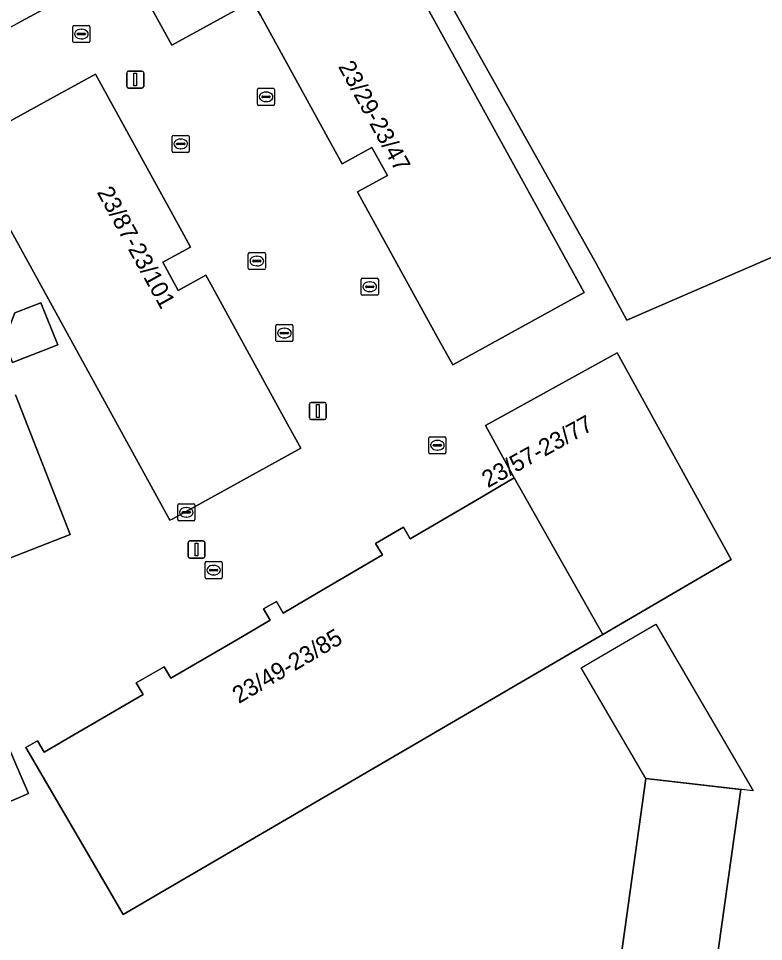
# Model space of a CAD drawing. Extents: x 161087 to 161926, y 382572 to 383873.
# Drawn here: x 161788.9 to 161832.5, y 382703.7 to 382757.7 of the extents above; entities that cross this region are included whole.
import ezdxf

# ---------------------------------------------------------------- set-up
doc = ezdxf.new("R2010")
doc.units = 0
for name, color, linetype in [('IMGEO_Brandkraan', 7, 'Continuous'), ('IMGEO_Erf', 7, 'Continuous'), ('IMGEO_Kolk', 7, 'Continuous'), ('IMGEO_Lichtmast', 7, 'Continuous'), ('IMGEO_Pand', 7, 'Continuous'), ('IMGEO_Pand_nummerreeks', 7, 'Continuous'), ('IMGEO_Pand_vergunning_verleend', 7, 'Continuous')]:
    doc.layers.add(name, color=color, linetype=linetype)

msp = doc.modelspace()

# ---------------------------------------------------------------- linework, layer by layer
at = {"layer": 'IMGEO_Brandkraan'}
for p, q in [((161802.377, 382743.063), (161802.377, 382743.915)), ((161802.452, 382743.989), (161803.304, 382743.989)), ((161803.378, 382743.915), (161803.378, 382743.063)), ((161802.636, 382743.483), (161802.636, 382743.495)), ((161803.074, 382743.446), (161802.676, 382743.446)), ((161802.679, 382743.532), (161803.077, 382743.532)), ((161802.865, 382743.769), (161802.89, 382743.769)), ((161803.12, 382743.495), (161803.12, 382743.483)), ((161803.304, 382742.989), (161802.452, 382742.989)), ((161802.888, 382743.209), (161802.863, 382743.209)), ((161798.253, 382728.36), (161798.253, 382729.212)), ((161798.328, 382729.286), (161799.18, 382729.286)), ((161798.512, 382728.78), (161798.512, 382728.792)), ((161798.555, 382728.829), (161798.953, 382728.829)), ((161798.741, 382729.066), (161798.766, 382729.066)), ((161798.996, 382728.792), (161798.996, 382728.78)), ((161799.254, 382729.212), (161799.254, 382728.36)), ((161799.18, 382728.286), (161798.328, 382728.286)), ((161798.95, 382728.743), (161798.552, 382728.743)), ((161798.764, 382728.506), (161798.739, 382728.506))]:
    msp.add_line(p, q, dxfattribs=at)
for points in [[(161802.377, 382743.063), (161802.377, 382743.915)], [(161802.452, 382743.989), (161803.304, 382743.989)], [(161803.378, 382743.915), (161803.378, 382743.063)], [(161803.304, 382742.989), (161802.452, 382742.989)], [(161798.253, 382728.36), (161798.253, 382729.212)], [(161798.328, 382729.286), (161799.18, 382729.286)], [(161799.254, 382729.212), (161799.254, 382728.36)], [(161799.18, 382728.286), (161798.328, 382728.286)]]:
    msp.add_lwpolyline(points, dxfattribs=at)
for centre, radius, start, end in [((161802.454, 382743.913), 0.0765, 91.552, 178.448), ((161802.454, 382743.913), 0.0765, 91.552, 178.448), ((161803.302, 382743.913), 0.0765, 1.552, 88.448), ((161803.302, 382743.913), 0.0765, 1.552, 88.448), ((161802.676, 382743.492), 0.0403, 85.8775, 175.7526), ((161802.673, 382743.482), 0.0366, 178.938, 274.7102), ((161803.077, 382743.489), 0.043, 264.8664, 352.4533), ((161803.081, 382743.494), 0.0386, 1.7309, 96.639), ((161802.454, 382743.065), 0.0765, 181.552, 268.448), ((161802.454, 382743.065), 0.0765, 181.552, 268.448), ((161803.302, 382743.065), 0.0765, 271.552, 358.448), ((161803.302, 382743.065), 0.0765, 271.552, 358.448), ((161798.33, 382729.21), 0.0765, 91.552, 178.448), ((161798.33, 382729.21), 0.0765, 91.552, 178.448), ((161798.552, 382728.789), 0.0403, 85.8775, 175.7526), ((161798.549, 382728.779), 0.0366, 178.938, 274.7102), ((161798.953, 382728.786), 0.043, 264.8664, 352.4533), ((161798.957, 382728.791), 0.0386, 1.7309, 96.639), ((161799.178, 382729.21), 0.0765, 1.552, 88.448), ((161799.178, 382729.21), 0.0765, 1.552, 88.448), ((161798.33, 382728.362), 0.0765, 181.552, 268.448), ((161798.33, 382728.362), 0.0765, 181.552, 268.448), ((161799.178, 382728.362), 0.0765, 271.552, 358.448), ((161799.178, 382728.362), 0.0765, 271.552, 358.448)]:
    msp.add_arc(centre, radius, start, end, dxfattribs=at)
for centre, major_axis, ratio, start_param, end_param in [((161802.864, 382743.489), (-0.387, 0.002), 0.722429, 4.712389, 7.853982), ((161802.889, 382743.489), (-0.39, 0.002), 0.717154, 1.570796, 4.712389), ((161798.74, 382728.786), (-0.387, 0.002), 0.722429, 4.712389, 7.853982), ((161798.765, 382728.786), (-0.39, 0.002), 0.717154, 1.570796, 4.712389)]:
    msp.add_ellipse(centre, major_axis=major_axis, ratio=ratio, start_param=start_param, end_param=end_param, dxfattribs=at)
at = {"layer": 'IMGEO_Erf'}
for points in [[(161803.093, 382757.868), (161802.608, 382758.688), (161797.899, 382756.116), (161793.667, 382763.818), (161794.577, 382764.319), (161801.727, 382768.254), (161806.068, 382770.643), (161810.325, 382762.902), (161822.015, 382741.645), (161814.33, 382737.412), (161813.548, 382738.832), (161809.152, 382746.816), (161808.758, 382747.532), (161810.515, 382748.49), (161809.611, 382750.138), (161807.858, 382749.177), (161807.453, 382749.914)], [(161797.962, 382728.415), (161797.788, 382728.319), (161785.753, 382750.218), (161791.191, 382753.197), (161793.435, 382754.427), (161794.2, 382753.036), (161798.607, 382745.023), (161799.005, 382744.299), (161797.372, 382743.432), (161798.28, 382741.775), (161799.902, 382742.664), (161800.287, 382741.962), (161804.675, 382733.953), (161805.453, 382732.533)], [(161788.579, 382737.55), (161788.088, 382738.792), (161788.733, 382740.452), (161790.249, 382741.048), (161791.235, 382738.594)], [(161803.657, 382722.469), (161803.262, 382723.141), (161804.031, 382723.569), (161804.411, 382722.888), (161806.356, 382724.028), (161810.224, 382726.296), (161809.818, 382726.971), (161811.455, 382727.923), (161811.851, 382727.243), (161815.677, 382729.48), (161817.929, 382730.796), (161816.247, 382733.866), (161823.943, 382738.127), (161830.622, 382726.017), (161823.114, 382721.632), (161795.066, 382705.25), (161794.06, 382706.978), (161789.37, 382715.034), (161790.044, 382715.425), (161790.436, 382714.751), (161792.404, 382715.899), (161796.23, 382718.132), (161795.823, 382718.802), (161797.464, 382719.751), (161797.854, 382719.076), (161801.705, 382721.328)], [(161825.634, 382713.206), (161831.172, 382712.574), (161829.503, 382700.65), (161823.984, 382701.422)]]:
    msp.add_lwpolyline(points, close=True, dxfattribs=at)
for points in [[(161837.83, 382745.8), (161831.129, 382742.893), (161824.517, 382740.025), (161822.714, 382743.348), (161811.318, 382763.682)], [(161792.002, 382759.112), (161788.908, 382757.413)], [(161788.77, 382735.655), (161791.956, 382727.48), (161787.457, 382725.726)], [(161788.237, 382715.327), (161789.523, 382712.339), (161785.528, 382710.619)]]:
    msp.add_lwpolyline(points, dxfattribs=at)
at = {"layer": 'IMGEO_Kolk'}
for p, q in [((161792.116, 382756.345), (161792.116, 382757.197)), ((161792.191, 382757.271), (161793.043, 382757.271)), ((161792.604, 382757.051), (161792.629, 382757.051)), ((161793.117, 382757.197), (161793.117, 382756.345)), ((161792.375, 382756.765), (161792.375, 382756.777)), ((161792.813, 382756.728), (161792.415, 382756.728)), ((161792.418, 382756.814), (161792.816, 382756.814)), ((161792.627, 382756.491), (161792.602, 382756.491)), ((161792.859, 382756.777), (161792.859, 382756.765)), ((161793.043, 382756.271), (161792.191, 382756.271)), ((161802.916, 382752.671), (161802.916, 382753.523)), ((161802.991, 382753.597), (161803.843, 382753.597)), ((161803.175, 382753.091), (161803.175, 382753.103)), ((161803.218, 382753.14), (161803.616, 382753.14)), ((161803.404, 382753.377), (161803.429, 382753.377)), ((161803.659, 382753.103), (161803.659, 382753.091)), ((161803.917, 382753.523), (161803.917, 382752.671)), ((161803.843, 382752.597), (161802.991, 382752.597)), ((161803.613, 382753.054), (161803.215, 382753.054)), ((161803.427, 382752.817), (161803.402, 382752.817)), ((161797.923, 382749.917), (161797.923, 382750.769)), ((161797.998, 382750.843), (161798.85, 382750.843)), ((161798.225, 382750.386), (161798.623, 382750.386)), ((161798.411, 382750.623), (161798.436, 382750.623)), ((161798.924, 382750.769), (161798.924, 382749.917)), ((161798.85, 382749.843), (161797.998, 382749.843)), ((161798.182, 382750.337), (161798.182, 382750.349)), ((161798.62, 382750.3), (161798.222, 382750.3)), ((161798.434, 382750.063), (161798.409, 382750.063)), ((161798.666, 382750.349), (161798.666, 382750.337)), ((161808.982, 382741.56), (161808.982, 382742.412)), ((161809.057, 382742.486), (161809.909, 382742.486)), ((161809.47, 382742.266), (161809.495, 382742.266)), ((161809.983, 382742.412), (161809.983, 382741.56)), ((161809.241, 382741.98), (161809.241, 382741.992)), ((161809.679, 382741.943), (161809.281, 382741.943)), ((161809.284, 382742.029), (161809.682, 382742.029)), ((161809.725, 382741.992), (161809.725, 382741.98)), ((161809.909, 382741.486), (161809.057, 382741.486)), ((161809.493, 382741.706), (161809.468, 382741.706)), ((161803.987, 382738.849), (161803.987, 382739.701)), ((161804.062, 382739.775), (161804.914, 382739.775)), ((161804.988, 382739.701), (161804.988, 382738.849)), ((161804.246, 382739.269), (161804.246, 382739.281)), ((161804.684, 382739.232), (161804.286, 382739.232)), ((161804.289, 382739.318), (161804.687, 382739.318)), ((161804.475, 382739.555), (161804.5, 382739.555)), ((161804.73, 382739.281), (161804.73, 382739.269)), ((161804.914, 382738.775), (161804.062, 382738.775)), ((161804.498, 382738.995), (161804.473, 382738.995)), ((161812.934, 382732.284), (161812.934, 382733.136)), ((161813.009, 382733.21), (161813.861, 382733.21)), ((161813.935, 382733.136), (161813.935, 382732.284)), ((161813.193, 382732.704), (161813.193, 382732.716)), ((161813.631, 382732.667), (161813.233, 382732.667)), ((161813.236, 382732.753), (161813.634, 382732.753)), ((161813.422, 382732.99), (161813.447, 382732.99)), ((161813.677, 382732.716), (161813.677, 382732.704)), ((161813.861, 382732.21), (161813.009, 382732.21)), ((161813.445, 382732.43), (161813.42, 382732.43)), ((161799.851, 382724.977), (161799.851, 382725.829)), ((161799.926, 382725.903), (161800.778, 382725.903)), ((161800.339, 382725.683), (161800.364, 382725.683)), ((161800.852, 382725.829), (161800.852, 382724.977)), ((161800.11, 382725.397), (161800.11, 382725.409)), ((161800.548, 382725.36), (161800.15, 382725.36)), ((161800.153, 382725.446), (161800.551, 382725.446)), ((161800.362, 382725.123), (161800.337, 382725.123)), ((161800.594, 382725.409), (161800.594, 382725.397)), ((161800.778, 382724.903), (161799.926, 382724.903))]:
    msp.add_line(p, q, dxfattribs=at)
for points in [[(161792.116, 382756.345), (161792.116, 382757.197)], [(161792.191, 382757.271), (161793.043, 382757.271)], [(161793.117, 382757.197), (161793.117, 382756.345)], [(161793.043, 382756.271), (161792.191, 382756.271)], [(161802.916, 382752.671), (161802.916, 382753.523)], [(161802.991, 382753.597), (161803.843, 382753.597)], [(161803.917, 382753.523), (161803.917, 382752.671)], [(161803.843, 382752.597), (161802.991, 382752.597)], [(161797.923, 382749.917), (161797.923, 382750.769)], [(161797.998, 382750.843), (161798.85, 382750.843)], [(161798.924, 382750.769), (161798.924, 382749.917)], [(161798.85, 382749.843), (161797.998, 382749.843)], [(161808.982, 382741.56), (161808.982, 382742.412)], [(161809.057, 382742.486), (161809.909, 382742.486)], [(161809.983, 382742.412), (161809.983, 382741.56)], [(161809.909, 382741.486), (161809.057, 382741.486)], [(161803.987, 382738.849), (161803.987, 382739.701)], [(161804.062, 382739.775), (161804.914, 382739.775)], [(161804.988, 382739.701), (161804.988, 382738.849)], [(161804.914, 382738.775), (161804.062, 382738.775)], [(161812.934, 382732.284), (161812.934, 382733.136)], [(161813.009, 382733.21), (161813.861, 382733.21)], [(161813.935, 382733.136), (161813.935, 382732.284)], [(161813.861, 382732.21), (161813.009, 382732.21)], [(161799.851, 382724.977), (161799.851, 382725.829)], [(161799.926, 382725.903), (161800.778, 382725.903)], [(161800.852, 382725.829), (161800.852, 382724.977)], [(161800.778, 382724.903), (161799.926, 382724.903)]]:
    msp.add_lwpolyline(points, dxfattribs=at)
for centre, radius, start, end in [((161792.193, 382757.195), 0.0765, 91.552, 178.448), ((161792.193, 382757.195), 0.0765, 91.552, 178.448), ((161793.041, 382757.195), 0.0765, 1.552, 88.448), ((161793.041, 382757.195), 0.0765, 1.552, 88.448), ((161792.193, 382756.347), 0.0765, 181.552, 268.448), ((161792.193, 382756.347), 0.0765, 181.552, 268.448), ((161792.415, 382756.774), 0.0403, 85.8775, 175.7526), ((161792.412, 382756.764), 0.0366, 178.938, 274.7102), ((161792.816, 382756.771), 0.043, 264.8664, 352.4533), ((161792.82, 382756.776), 0.0386, 1.7309, 96.639), ((161793.041, 382756.347), 0.0765, 271.552, 358.448), ((161793.041, 382756.347), 0.0765, 271.552, 358.448), ((161802.993, 382753.521), 0.0765, 91.552, 178.448), ((161802.993, 382753.521), 0.0765, 91.552, 178.448), ((161803.215, 382753.1), 0.0403, 85.8775, 175.7526), ((161803.212, 382753.09), 0.0366, 178.938, 274.7102), ((161803.616, 382753.097), 0.043, 264.8664, 352.4533), ((161803.62, 382753.102), 0.0386, 1.7309, 96.639), ((161803.841, 382753.521), 0.0765, 1.552, 88.448), ((161803.841, 382753.521), 0.0765, 1.552, 88.448), ((161802.993, 382752.673), 0.0765, 181.552, 268.448), ((161802.993, 382752.673), 0.0765, 181.552, 268.448), ((161803.841, 382752.673), 0.0765, 271.552, 358.448), ((161803.841, 382752.673), 0.0765, 271.552, 358.448), ((161798, 382750.767), 0.0765, 91.552, 178.448), ((161798, 382750.767), 0.0765, 91.552, 178.448), ((161798.222, 382750.346), 0.0403, 85.8775, 175.7526), ((161798.627, 382750.348), 0.0386, 1.7309, 96.639), ((161798.848, 382750.767), 0.0765, 1.552, 88.448), ((161798.848, 382750.767), 0.0765, 1.552, 88.448), ((161798, 382749.919), 0.0765, 181.552, 268.448), ((161798, 382749.919), 0.0765, 181.552, 268.448), ((161798.219, 382750.336), 0.0366, 178.938, 274.7102), ((161798.623, 382750.343), 0.043, 264.8664, 352.4533), ((161798.848, 382749.919), 0.0765, 271.552, 358.448), ((161798.848, 382749.919), 0.0765, 271.552, 358.448), ((161809.059, 382742.41), 0.0765, 91.552, 178.448), ((161809.059, 382742.41), 0.0765, 91.552, 178.448), ((161809.907, 382742.41), 0.0765, 1.552, 88.448), ((161809.907, 382742.41), 0.0765, 1.552, 88.448), ((161809.281, 382741.989), 0.0403, 85.8775, 175.7526), ((161809.278, 382741.979), 0.0366, 178.938, 274.7102), ((161809.682, 382741.986), 0.043, 264.8664, 352.4533), ((161809.686, 382741.991), 0.0386, 1.7309, 96.639), ((161809.059, 382741.562), 0.0765, 181.552, 268.448), ((161809.059, 382741.562), 0.0765, 181.552, 268.448), ((161809.907, 382741.562), 0.0765, 271.552, 358.448), ((161809.907, 382741.562), 0.0765, 271.552, 358.448), ((161804.064, 382739.699), 0.0765, 91.552, 178.448), ((161804.064, 382739.699), 0.0765, 91.552, 178.448), ((161804.912, 382739.699), 0.0765, 1.552, 88.448), ((161804.912, 382739.699), 0.0765, 1.552, 88.448), ((161804.286, 382739.278), 0.0403, 85.8775, 175.7526), ((161804.283, 382739.268), 0.0366, 178.938, 274.7102), ((161804.687, 382739.275), 0.043, 264.8664, 352.4533), ((161804.691, 382739.28), 0.0386, 1.7309, 96.639), ((161804.064, 382738.851), 0.0765, 181.552, 268.448), ((161804.064, 382738.851), 0.0765, 181.552, 268.448), ((161804.912, 382738.851), 0.0765, 271.552, 358.448), ((161804.912, 382738.851), 0.0765, 271.552, 358.448), ((161813.011, 382733.134), 0.0765, 91.552, 178.448), ((161813.011, 382733.134), 0.0765, 91.552, 178.448), ((161813.859, 382733.134), 0.0765, 1.552, 88.448), ((161813.859, 382733.134), 0.0765, 1.552, 88.448), ((161813.233, 382732.713), 0.0403, 85.8775, 175.7526), ((161813.23, 382732.703), 0.0366, 178.938, 274.7102), ((161813.634, 382732.71), 0.043, 264.8664, 352.4533), ((161813.638, 382732.715), 0.0386, 1.7309, 96.639), ((161813.011, 382732.286), 0.0765, 181.552, 268.448), ((161813.011, 382732.286), 0.0765, 181.552, 268.448), ((161813.859, 382732.286), 0.0765, 271.552, 358.448), ((161813.859, 382732.286), 0.0765, 271.552, 358.448), ((161799.928, 382725.827), 0.0765, 91.552, 178.448), ((161799.928, 382725.827), 0.0765, 91.552, 178.448), ((161800.776, 382725.827), 0.0765, 1.552, 88.448), ((161800.776, 382725.827), 0.0765, 1.552, 88.448), ((161799.928, 382724.979), 0.0765, 181.552, 268.448), ((161799.928, 382724.979), 0.0765, 181.552, 268.448), ((161800.15, 382725.406), 0.0403, 85.8775, 175.7526), ((161800.147, 382725.396), 0.0366, 178.938, 274.7102), ((161800.551, 382725.403), 0.043, 264.8664, 352.4533), ((161800.555, 382725.408), 0.0386, 1.7309, 96.639), ((161800.776, 382724.979), 0.0765, 271.552, 358.448), ((161800.776, 382724.979), 0.0765, 271.552, 358.448)]:
    msp.add_arc(centre, radius, start, end, dxfattribs=at)
for centre, major_axis, ratio, start_param, end_param in [((161792.603, 382756.771), (-0.387, 0.002), 0.722429, 4.712389, 7.853982), ((161792.628, 382756.771), (-0.39, 0.002), 0.717154, 1.570796, 4.712389), ((161803.403, 382753.097), (-0.387, 0.002), 0.722429, 4.712389, 7.853982), ((161803.428, 382753.097), (-0.39, 0.002), 0.717154, 1.570796, 4.712389), ((161798.41, 382750.343), (-0.387, 0.002), 0.722429, 4.712389, 7.853982), ((161798.435, 382750.343), (-0.39, 0.002), 0.717154, 1.570796, 4.712389), ((161809.469, 382741.986), (-0.387, 0.002), 0.722429, 4.712389, 7.853982), ((161809.494, 382741.986), (-0.39, 0.002), 0.717154, 1.570796, 4.712389), ((161804.474, 382739.275), (-0.387, 0.002), 0.722429, 4.712389, 7.853982), ((161804.499, 382739.275), (-0.39, 0.002), 0.717154, 1.570796, 4.712389), ((161813.421, 382732.71), (-0.387, 0.002), 0.722429, 4.712389, 7.853982), ((161813.446, 382732.71), (-0.39, 0.002), 0.717154, 1.570796, 4.712389), ((161800.338, 382725.403), (-0.387, 0.002), 0.722429, 4.712389, 7.853982), ((161800.363, 382725.403), (-0.39, 0.002), 0.717154, 1.570796, 4.712389)]:
    msp.add_ellipse(centre, major_axis=major_axis, ratio=ratio, start_param=start_param, end_param=end_param, dxfattribs=at)
at = {"layer": 'IMGEO_Lichtmast'}
for p, q in [((161795.27, 382753.708), (161795.27, 382754.508)), ((161795.27, 382754.508), (161795.27, 382753.708)), ((161795.37, 382754.608), (161796.16, 382754.608)), ((161796.16, 382754.608), (161795.37, 382754.608)), ((161796.26, 382754.508), (161796.26, 382753.708)), ((161796.26, 382753.708), (161796.26, 382754.508)), ((161796.16, 382753.608), (161795.37, 382753.608)), ((161795.37, 382753.608), (161796.16, 382753.608)), ((161805.947, 382734.313), (161805.947, 382735.113)), ((161805.947, 382735.113), (161805.947, 382734.313)), ((161806.047, 382735.213), (161806.837, 382735.213)), ((161806.837, 382735.213), (161806.047, 382735.213)), ((161806.937, 382735.113), (161806.937, 382734.313)), ((161806.937, 382734.313), (161806.937, 382735.113)), ((161806.837, 382734.213), (161806.047, 382734.213)), ((161806.047, 382734.213), (161806.837, 382734.213)), ((161798.851, 382726.211), (161798.851, 382727.011)), ((161798.851, 382727.011), (161798.851, 382726.211)), ((161798.951, 382727.111), (161799.741, 382727.111)), ((161799.741, 382727.111), (161798.951, 382727.111)), ((161799.841, 382727.011), (161799.841, 382726.211)), ((161799.841, 382726.211), (161799.841, 382727.011)), ((161799.741, 382726.111), (161798.951, 382726.111)), ((161798.951, 382726.111), (161799.741, 382726.111))]:
    msp.add_line(p, q, dxfattribs=at)
for points in [[(161795.69, 382754.483), (161795.84, 382754.483), (161795.84, 382753.733), (161795.69, 382753.733), (161795.69, 382754.483)], [(161806.367, 382735.088), (161806.517, 382735.088), (161806.517, 382734.338), (161806.367, 382734.338), (161806.367, 382735.088)], [(161799.271, 382726.986), (161799.421, 382726.986), (161799.421, 382726.236), (161799.271, 382726.236), (161799.271, 382726.986)]]:
    msp.add_lwpolyline(points, dxfattribs=at)
for centre, start, end in [((161795.37, 382754.508), 90, 180), ((161795.37, 382754.508), 90, 180), ((161796.16, 382754.508), 0, 90), ((161796.16, 382754.508), 360, 90), ((161795.37, 382753.708), 180, 270), ((161795.37, 382753.708), 180, 270), ((161796.16, 382753.708), 270, 0), ((161796.16, 382753.708), 270, 0), ((161806.047, 382735.113), 90, 180), ((161806.047, 382735.113), 90, 180), ((161806.837, 382735.113), 0, 90), ((161806.837, 382735.113), 360, 90), ((161806.047, 382734.313), 180, 270), ((161806.047, 382734.313), 180, 270), ((161806.837, 382734.313), 270, 0), ((161806.837, 382734.313), 270, 0), ((161798.951, 382727.011), 90, 180), ((161798.951, 382727.011), 90, 180), ((161799.741, 382727.011), 0, 90), ((161799.741, 382727.011), 360, 90), ((161798.951, 382726.211), 180, 270), ((161798.951, 382726.211), 180, 270), ((161799.741, 382726.211), 270, 0), ((161799.741, 382726.211), 270, 0)]:
    msp.add_arc(centre, 0.1, start, end, dxfattribs=at)
at = {"layer": 'IMGEO_Pand'}
for points in [[(161842.754, 382761.157), (161841.02, 382760.404), (161839.041, 382764.787), (161852.576, 382770.77), (161849.885, 382776.163), (161846.952, 382781.596), (161826.285, 382772.036), (161824.514, 382775.865), (161808.664, 382768.534), (161811.318, 382763.682), (161822.714, 382743.348), (161824.517, 382740.025), (161831.129, 382742.893), (161837.83, 382745.8), (161845.906, 382749.6), (161845.712, 382750), (161844.482, 382752.573), (161844.36, 382752.828), (161842.152, 382757.833), (161842.546, 382758.006)], [(161810.325, 382762.902), (161806.068, 382770.643), (161801.727, 382768.254), (161794.577, 382764.319), (161793.667, 382763.818), (161797.899, 382756.116), (161802.608, 382758.688)], [(161810.325, 382762.902), (161802.608, 382758.688), (161803.093, 382757.868), (161807.453, 382749.914), (161807.858, 382749.177), (161809.611, 382750.138), (161810.515, 382748.49), (161808.758, 382747.532), (161809.152, 382746.816), (161813.548, 382738.832), (161814.33, 382737.412), (161822.015, 382741.645)], [(161794.2, 382753.036), (161793.435, 382754.427), (161791.191, 382753.197), (161785.753, 382750.218), (161797.788, 382728.319), (161797.962, 382728.415), (161805.453, 382732.533), (161804.675, 382733.953), (161800.287, 382741.962), (161799.902, 382742.664), (161798.28, 382741.775), (161797.372, 382743.432), (161799.005, 382744.299), (161798.607, 382745.023)], [(161790.249, 382741.048), (161788.733, 382740.452), (161788.088, 382738.792), (161788.579, 382737.55), (161791.235, 382738.594)], [(161817.929, 382730.796), (161823.114, 382721.632), (161830.622, 382726.017), (161823.943, 382738.127), (161816.247, 382733.866)], [(161817.929, 382730.796), (161815.677, 382729.48), (161811.851, 382727.243), (161811.455, 382727.923), (161809.818, 382726.971), (161810.224, 382726.296), (161806.356, 382724.028), (161804.411, 382722.888), (161804.031, 382723.569), (161803.262, 382723.141), (161803.657, 382722.469), (161801.705, 382721.328), (161797.854, 382719.076), (161797.464, 382719.751), (161795.823, 382718.802), (161796.23, 382718.132), (161792.404, 382715.899), (161790.436, 382714.751), (161790.044, 382715.425), (161789.37, 382715.034), (161794.06, 382706.978), (161795.066, 382705.25), (161823.114, 382721.632)], [(161787.005, 382699.938), (161784.706, 382705.422), (161787.258, 382706.492), (161785.598, 382710.452), (161785.528, 382710.619), (161789.523, 382712.339), (161788.237, 382715.327), (161787.603, 382715.06), (161777.137, 382710.655), (161778.153, 382708.232), (161774.101, 382706.534), (161778.499, 382696.044), (161786.485, 382699.392), (161786.368, 382699.671)], [(161823.984, 382701.422), (161829.503, 382700.65), (161831.172, 382712.574), (161825.634, 382713.206)]]:
    msp.add_lwpolyline(points, close=True, dxfattribs=at)
for points in [[(161760.362, 382759.021), (161754.87, 382756.874), (161754.496, 382757.83), (161745.004, 382754.118), (161745.052, 382753.994), (161745.224, 382753.561), (161745.232, 382753.541), (161745.521, 382753.653), (161747.027, 382753.458), (161747.078, 382753.327), (161756.299, 382756.897), (161758.09, 382752.271), (161747.346, 382748.113), (161748.078, 382746.268), (161749.728, 382742.115), (161763.782, 382747.61), (161763.929, 382747.233), (161786.294, 382756.038), (161786.424, 382756.091), (161788.908, 382757.413), (161792.002, 382759.112)], [(161787.457, 382725.726), (161791.956, 382727.48), (161788.77, 382735.655)]]:
    msp.add_lwpolyline(points, dxfattribs=at)
at = {"layer": 'IMGEO_Pand_vergunning_verleend'}
msp.add_lwpolyline([(161821.843, 382719.683), (161826.208, 382722.233), (161831.898, 382712.491), (161825.634, 382713.206)], close=True, dxfattribs=at)

# ---------------------------------------------------------------- texts
at = {"layer": 'IMGEO_Pand_nummerreeks'}
for s, rotation, p in [('23/29-23/47', 298.6884, (161807.611, 382754.877)), ('23/87-23/101', 298.751, (161793.497, 382747.521)), ('23/57-23/77', 28.9755, (161816.386, 382730.193)), ('23/49-23/85', 30.3821, (161801.818, 382717.565))]:
    msp.add_text(s, height=1, rotation=rotation, dxfattribs=at).set_placement(p)

doc.saveas('drawing.dxf')
